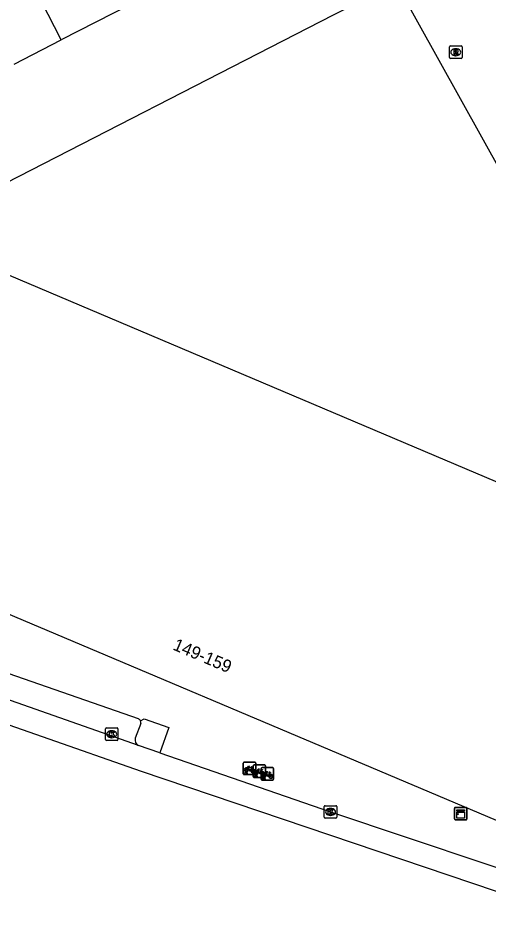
# Model space of a CAD drawing. Extents: x 161771 to 163125, y 382479 to 383177.
# Drawn here: x 162326.1 to 162363.8, y 382570.3 to 382642.4 of the extents above; entities that cross this region are included whole.
import ezdxf

# ---------------------------------------------------------------- set-up
doc = ezdxf.new("R2010")
doc.units = 0
for name, color, linetype in [('IMGEO_Fietsenrek', 7, 'Continuous'), ('IMGEO_Kast', 7, 'Continuous'), ('IMGEO_Kolk', 7, 'Continuous'), ('IMGEO_Pand', 7, 'Continuous'), ('IMGEO_Pand_nummerreeks', 7, 'Continuous'), ('IMGEO_Parkeervlak_open', 7, 'Continuous'), ('IMGEO_Rijbaan_lokaal_gesloten', 7, 'Continuous'), ('IMGEO_Rijbaan_lokaal_open', 7, 'Continuous'), ('IMGEO_Rioolput', 7, 'Continuous'), ('IMGEO_Voetpad_open', 7, 'Continuous')]:
    doc.layers.add(name, color=color, linetype=linetype)

msp = doc.modelspace()

# ---------------------------------------------------------------- linework, layer by layer
at = {"layer": 'IMGEO_Fietsenrek'}
for p, q in [((162344.179, 382581.681), (162344.179, 382582.522)), ((162344.179, 382582.522), (162344.179, 382581.681)), ((162344.254, 382582.606), (162345.095, 382582.606)), ((162345.095, 382582.606), (162344.254, 382582.606)), ((162345.042, 382582.385), (162345.883, 382582.385)), ((162345.883, 382582.385), (162345.042, 382582.385)), ((162345.179, 382582.531), (162345.179, 382581.69)), ((162345.179, 382581.69), (162345.179, 382582.531)), ((162344.306, 382581.69), (162344.345, 382581.85)), ((162344.34, 382581.69), (162344.306, 382581.69)), ((162344.375, 382581.838), (162344.34, 382581.69)), ((162344.417, 382581.862), (162344.416, 382581.866)), ((162344.458, 382581.69), (162344.424, 382581.832)), ((162344.448, 382581.873), (162344.449, 382581.866)), ((162344.456, 382581.836), (162344.491, 382581.69)), ((162344.491, 382581.69), (162344.458, 382581.69)), ((162344.866, 382582.155), (162344.902, 382582.06)), ((162344.967, 382581.46), (162344.967, 382582.301)), ((162344.967, 382582.301), (162344.967, 382581.46)), ((162345.094, 382581.469), (162345.133, 382581.629)), ((162345.163, 382581.617), (162345.128, 382581.469)), ((162345.205, 382581.641), (162345.204, 382581.645)), ((162345.236, 382581.652), (162345.237, 382581.645)), ((162345.244, 382581.615), (162345.279, 382581.469)), ((162345.613, 382581.246), (162345.613, 382582.087)), ((162345.613, 382582.087), (162345.613, 382581.246)), ((162345.654, 382581.934), (162345.69, 382581.839)), ((162345.688, 382582.171), (162346.529, 382582.171)), ((162346.529, 382582.171), (162345.688, 382582.171)), ((162345.967, 382582.31), (162345.967, 382581.469)), ((162345.967, 382581.469), (162345.967, 382582.31)), ((162346.3, 382581.72), (162346.336, 382581.625)), ((162346.613, 382582.096), (162346.613, 382581.255)), ((162346.613, 382581.255), (162346.613, 382582.096)), ((162345.104, 382581.606), (162344.263, 382581.606)), ((162344.263, 382581.606), (162345.104, 382581.606)), ((162345.892, 382581.385), (162345.051, 382581.385)), ((162345.051, 382581.385), (162345.892, 382581.385)), ((162345.128, 382581.469), (162345.094, 382581.469)), ((162345.246, 382581.469), (162345.212, 382581.611)), ((162345.279, 382581.469), (162345.246, 382581.469)), ((162346.538, 382581.171), (162345.697, 382581.171)), ((162345.697, 382581.171), (162346.538, 382581.171)), ((162345.74, 382581.255), (162345.779, 382581.415)), ((162345.774, 382581.255), (162345.74, 382581.255)), ((162345.809, 382581.403), (162345.774, 382581.255)), ((162345.851, 382581.427), (162345.85, 382581.431)), ((162345.892, 382581.255), (162345.858, 382581.397)), ((162345.882, 382581.438), (162345.883, 382581.431)), ((162345.89, 382581.401), (162345.925, 382581.255)), ((162345.925, 382581.255), (162345.892, 382581.255))]:
    msp.add_line(p, q, dxfattribs=at)
for points in [[(162344.513, 382582.08), (162344.461, 382581.99), (162344.421, 382581.965), (162344.422, 382582.012), (162344.477, 382582.106)], [(162344.492, 382582.132), (162344.587, 382582.296), (162344.673, 382582.282), (162344.675, 382582.273), (162344.619, 382582.262), (162344.592, 382582.217), (162344.848, 382582.176)], [(162344.788, 382581.888), (162344.738, 382581.888), (162344.547, 382582.139), (162344.528, 382582.107)], [(162344.835, 382582.151), (162344.578, 382582.192), (162344.561, 382582.163), (162344.728, 382581.943), (162344.835, 382582.151)], [(162344.883, 382582.053), (162344.853, 382582.13), (162344.744, 382581.912), (162344.787, 382581.912)], [(162344.817, 382581.912), (162344.937, 382581.911), (162344.893, 382582.025)], [(162344.913, 382582.032), (162344.968, 382581.887), (162344.818, 382581.887)], [(162344.848, 382582.176), (162344.873, 382582.225), (162344.867, 382582.229), (162344.844, 382582.233), (162344.832, 382582.24), (162344.831, 382582.243), (162344.833, 382582.248), (162344.928, 382582.233), (162344.93, 382582.223), (162344.92, 382582.21), (162344.908, 382582.204), (162344.894, 382582.21), (162344.866, 382582.155)], [(162345.301, 382581.859), (162345.249, 382581.769), (162345.209, 382581.744), (162345.21, 382581.791), (162345.265, 382581.885)], [(162345.28, 382581.911), (162345.375, 382582.075), (162345.461, 382582.061), (162345.463, 382582.052), (162345.407, 382582.041), (162345.38, 382581.996), (162345.636, 382581.955)], [(162345.576, 382581.667), (162345.526, 382581.667), (162345.335, 382581.918), (162345.316, 382581.886)], [(162345.623, 382581.93), (162345.366, 382581.971), (162345.349, 382581.942), (162345.516, 382581.722), (162345.623, 382581.93)], [(162345.671, 382581.832), (162345.641, 382581.909), (162345.532, 382581.691), (162345.575, 382581.691)], [(162345.605, 382581.691), (162345.725, 382581.69), (162345.681, 382581.804)], [(162345.701, 382581.811), (162345.756, 382581.666), (162345.606, 382581.666)], [(162345.636, 382581.955), (162345.661, 382582.004), (162345.655, 382582.008), (162345.632, 382582.012), (162345.62, 382582.019), (162345.619, 382582.022), (162345.621, 382582.027), (162345.716, 382582.012), (162345.718, 382582.002), (162345.708, 382581.989), (162345.696, 382581.983), (162345.682, 382581.989), (162345.654, 382581.934)], [(162345.947, 382581.645), (162345.895, 382581.555), (162345.855, 382581.53), (162345.856, 382581.577), (162345.911, 382581.671)], [(162345.926, 382581.697), (162346.021, 382581.861), (162346.107, 382581.847), (162346.109, 382581.838), (162346.053, 382581.827), (162346.026, 382581.782), (162346.282, 382581.741)], [(162346.222, 382581.453), (162346.172, 382581.453), (162345.981, 382581.704), (162345.962, 382581.672)], [(162346.269, 382581.716), (162346.012, 382581.757), (162345.995, 382581.728), (162346.162, 382581.508), (162346.269, 382581.716)], [(162346.317, 382581.618), (162346.287, 382581.695), (162346.178, 382581.477), (162346.221, 382581.477)], [(162346.282, 382581.741), (162346.307, 382581.79), (162346.301, 382581.794), (162346.278, 382581.798), (162346.266, 382581.805), (162346.265, 382581.808), (162346.267, 382581.813), (162346.362, 382581.798), (162346.364, 382581.788), (162346.354, 382581.775), (162346.342, 382581.769), (162346.328, 382581.775), (162346.3, 382581.72)], [(162346.251, 382581.477), (162346.371, 382581.476), (162346.327, 382581.59)], [(162346.347, 382581.597), (162346.402, 382581.452), (162346.252, 382581.452)]]:
    msp.add_lwpolyline(points, dxfattribs=at)
for centre, radius, start, end in [((162344.257, 382582.528), 0.0779, 92.4484, 184.28452), ((162344.257, 382582.528), 0.0779, 92.4484, 184.28452), ((162345.045, 382582.307), 0.0779, 92.4484, 184.28452), ((162345.045, 382582.307), 0.0779, 92.4484, 184.28452), ((162345.101, 382582.528), 0.0779, 2.4484, 94.28452), ((162345.101, 382582.528), 0.0779, 2.4484, 94.28452), ((162345.889, 382582.307), 0.0779, 2.4484, 94.28452), ((162345.889, 382582.307), 0.0779, 2.4484, 94.28452), ((162344.257, 382581.684), 0.0779, 182.4484, 274.28452), ((162344.257, 382581.684), 0.0779, 182.4484, 274.28452), ((162344.419, 382581.991), 0.159, 62.67661, 242.13685), ((162344.419, 382581.991), 0.129, 63.31916, 238.90302), ((162344.399, 382581.862), 0.0499, 12.8025, 158.69338), ((162344.419, 382581.991), 0.159, 253.99666, 271.78671), ((162344.399, 382581.862), 0.0174, 12.8025, 163.45023), ((162344.419, 382581.991), 0.129, 253.41502, 269.02044), ((162344.419, 382581.991), 0.129, 283.60429, 43.43025), ((162344.419, 382581.991), 0.159, 283.5766, 46.60424), ((162344.946, 382581.907), 0.159, 113.3408, 178.32165), ((162344.946, 382581.907), 0.159, 187.0065, 105.77075), ((162344.946, 382581.907), 0.129, 113.92302, 177.95563), ((162344.946, 382581.907), 0.129, 188.67146, 104.58832), ((162345.207, 382581.77), 0.159, 62.67661, 242.13685), ((162345.207, 382581.77), 0.129, 63.31916, 238.90302), ((162345.101, 382581.684), 0.0779, 272.4484, 4.28452), ((162345.101, 382581.684), 0.0779, 272.4484, 4.28452), ((162345.187, 382581.641), 0.0499, 12.8025, 158.69338), ((162345.207, 382581.77), 0.159, 253.99666, 271.78671), ((162345.187, 382581.641), 0.0174, 12.8025, 163.45023), ((162345.207, 382581.77), 0.129, 253.41502, 269.02044), ((162345.207, 382581.77), 0.129, 283.60429, 43.43025), ((162345.207, 382581.77), 0.159, 283.5766, 46.60424), ((162345.734, 382581.686), 0.159, 113.3408, 178.32165), ((162345.734, 382581.686), 0.159, 187.0065, 105.77075), ((162345.734, 382581.686), 0.129, 113.92302, 177.95563), ((162345.734, 382581.686), 0.129, 188.67146, 104.58832), ((162345.691, 382582.093), 0.0779, 92.4484, 184.28452), ((162345.691, 382582.093), 0.0779, 92.4484, 184.28452), ((162345.853, 382581.556), 0.159, 62.67661, 242.13685), ((162345.853, 382581.556), 0.129, 63.31916, 238.90302), ((162345.853, 382581.556), 0.129, 283.60429, 43.43025), ((162345.853, 382581.556), 0.159, 283.5766, 46.60424), ((162346.38, 382581.472), 0.159, 113.3408, 178.32165), ((162346.38, 382581.472), 0.159, 187.0065, 105.77075), ((162346.535, 382582.093), 0.0779, 2.4484, 94.28452), ((162346.535, 382582.093), 0.0779, 2.4484, 94.28452), ((162345.045, 382581.463), 0.0779, 182.4484, 274.28452), ((162345.045, 382581.463), 0.0779, 182.4484, 274.28452), ((162345.691, 382581.249), 0.0779, 182.4484, 274.28452), ((162345.691, 382581.249), 0.0779, 182.4484, 274.28452), ((162345.833, 382581.427), 0.0499, 12.8025, 158.69338), ((162345.853, 382581.556), 0.159, 253.99666, 271.78671), ((162345.833, 382581.427), 0.0174, 12.8025, 163.45023), ((162345.853, 382581.556), 0.129, 253.41502, 269.02044), ((162345.889, 382581.463), 0.0779, 272.4484, 4.28452), ((162345.889, 382581.463), 0.0779, 272.4484, 4.28452), ((162346.38, 382581.472), 0.129, 113.92302, 177.95563), ((162346.38, 382581.472), 0.129, 188.67146, 104.58832), ((162346.535, 382581.249), 0.0779, 272.4484, 4.28452), ((162346.535, 382581.249), 0.0779, 272.4484, 4.28452)]:
    msp.add_arc(centre, radius, start, end, dxfattribs=at)
at = {"layer": 'IMGEO_Kast'}
for p, q in [((162361.122, 382578.055), (162361.122, 382578.896)), ((162361.122, 382578.896), (162361.122, 382578.055)), ((162361.197, 382578.98), (162362.038, 382578.98)), ((162362.038, 382578.98), (162361.197, 382578.98)), ((162362.122, 382578.905), (162362.122, 382578.064)), ((162362.122, 382578.064), (162362.122, 382578.905)), ((162362.047, 382577.98), (162361.206, 382577.98)), ((162361.206, 382577.98), (162362.047, 382577.98))]:
    msp.add_line(p, q, dxfattribs=at)
for points in [[(162361.317, 382578.77), (162361.917, 382578.77), (162361.917, 382578.685), (162361.317, 382578.685), (162361.317, 382578.77)], [(162361.317, 382578.595), (162361.917, 382578.595), (162361.917, 382578.106), (162361.317, 382578.106), (162361.317, 382578.595)]]:
    msp.add_lwpolyline(points, dxfattribs=at)
msp.add_circle((162361.401, 382578.444), 0.0377, dxfattribs=at)
for centre, start, end in [((162361.2, 382578.902), 92.4484, 184.28452), ((162361.2, 382578.902), 92.4484, 184.28452), ((162362.044, 382578.902), 2.4484, 94.28452), ((162362.044, 382578.902), 2.4484, 94.28452), ((162361.2, 382578.058), 182.4484, 274.28452), ((162361.2, 382578.058), 182.4484, 274.28452), ((162362.044, 382578.058), 272.4484, 4.28452), ((162362.044, 382578.058), 272.4484, 4.28452)]:
    msp.add_arc(centre, 0.0779, start, end, dxfattribs=at)
at = {"layer": 'IMGEO_Kolk'}
for p, q in [((162333.123, 382584.425), (162333.123, 382585.277)), ((162333.198, 382585.351), (162334.05, 382585.351)), ((162334.124, 382585.277), (162334.124, 382584.425)), ((162333.634, 382584.571), (162333.609, 382584.571)), ((162333.611, 382585.131), (162333.636, 382585.131)), ((162334.05, 382584.351), (162333.198, 382584.351)), ((162350.678, 382578.187), (162350.678, 382579.039)), ((162350.753, 382579.113), (162351.605, 382579.113)), ((162351.166, 382578.893), (162351.191, 382578.893)), ((162351.679, 382579.039), (162351.679, 382578.187)), ((162351.605, 382578.113), (162350.753, 382578.113)), ((162351.189, 382578.333), (162351.164, 382578.333))]:
    msp.add_line(p, q, dxfattribs=at)
for points in [[(162333.123, 382584.425), (162333.123, 382585.277)], [(162333.198, 382585.351), (162334.05, 382585.351)], [(162334.124, 382585.277), (162334.124, 382584.425)], [(162333.444, 382585.051), (162333.567, 382585.051), (162333.567, 382584.9), (162333.697, 382585.051), (162333.861, 382585.051), (162333.715, 382584.9), (162333.868, 382584.651), (162333.716, 382584.651), (162333.631, 382584.815), (162333.567, 382584.748), (162333.567, 382584.651), (162333.444, 382584.651), (162333.444, 382585.051)], [(162334.05, 382584.351), (162333.198, 382584.351)], [(162350.678, 382578.187), (162350.678, 382579.039)], [(162350.753, 382579.113), (162351.605, 382579.113)], [(162350.999, 382578.813), (162351.122, 382578.813), (162351.122, 382578.662), (162351.252, 382578.813), (162351.416, 382578.813), (162351.27, 382578.662), (162351.423, 382578.413), (162351.271, 382578.413), (162351.186, 382578.577), (162351.122, 382578.51), (162351.122, 382578.413), (162350.999, 382578.413), (162350.999, 382578.813)], [(162351.679, 382579.039), (162351.679, 382578.187)], [(162351.605, 382578.113), (162350.753, 382578.113)]]:
    msp.add_lwpolyline(points, dxfattribs=at)
for centre, start, end in [((162333.2, 382585.275), 91.55205, 178.44795), ((162333.2, 382585.275), 91.55205, 178.44795), ((162334.048, 382585.275), 1.55205, 88.44795), ((162334.048, 382585.275), 1.55205, 88.44795), ((162333.2, 382584.427), 181.55205, 268.44795), ((162333.2, 382584.427), 181.55205, 268.44795), ((162334.048, 382584.427), 271.55205, 358.44795), ((162334.048, 382584.427), 271.55205, 358.44795), ((162350.755, 382579.037), 91.55205, 178.44795), ((162350.755, 382579.037), 91.55205, 178.44795), ((162351.603, 382579.037), 1.55205, 88.44795), ((162351.603, 382579.037), 1.55205, 88.44795), ((162350.755, 382578.189), 181.55205, 268.44795), ((162350.755, 382578.189), 181.55205, 268.44795), ((162351.603, 382578.189), 271.55205, 358.44795), ((162351.603, 382578.189), 271.55205, 358.44795)]:
    msp.add_arc(centre, 0.0765, start, end, dxfattribs=at)
for centre, major_axis, ratio, start_param, end_param in [((162333.61, 382584.851), (-0.387, 0.002), 0.722429, 4.712389, 7.853982), ((162333.635, 382584.851), (-0.39, 0.002), 0.717154, 1.570796, 4.712389), ((162351.165, 382578.613), (-0.387, 0.002), 0.722429, 4.712389, 7.853982), ((162351.19, 382578.613), (-0.39, 0.002), 0.717154, 1.570796, 4.712389)]:
    msp.add_ellipse(centre, major_axis=major_axis, ratio=ratio, start_param=start_param, end_param=end_param, dxfattribs=at)
at = {"layer": 'IMGEO_Pand'}
for points in [[(162329.566, 382640.609), (162326.409, 382646.789), (162344.176, 382655.844), (162344.436, 382655.843), (162345.668, 382653.406), (162348.747, 382654.979)], [(162350.456, 382651.281), (162329.566, 382640.609)], [(162355.836, 382644.864), (162351.387, 382642.583), (162322.08, 382627.559), (162320.518, 382630.266), (162318.547, 382629.128), (162316.196, 382633.711)], [(162325.796, 382638.664), (162329.566, 382640.609)], [(162379.028, 382608.247), (162375.863, 382604.377), (162373.376, 382601.335), (162322.929, 382622.738)], [(162368.518, 382576.348), (162368.466, 382576.233), (162313.172, 382599.641)]]:
    msp.add_lwpolyline(points, dxfattribs=at)
at = {"layer": 'IMGEO_Parkeervlak_open'}
msp.add_lwpolyline([(162335.962, 382585.724), (162335.516, 382584.532)], dxfattribs=at)
for centre, radius, start, end in [((162335.594, 382585.759), 0.369, 354.60434, 25.37775), ((162335.988, 382584.385), 0.494, 162.70994, 245.64176)]:
    msp.add_arc(centre, radius, start, end, dxfattribs=at)
at = {"layer": 'IMGEO_Rijbaan_lokaal_gesloten'}
for points in [[(162370.099, 382570.33), (162336, 382581.86), (162312.157, 382590.208), (162289.771, 382599.475), (162259.358, 382612.5), (162215.386, 382631.365)], [(162335.784, 382583.935), (162312.409, 382592.158)], [(162337.494, 382583.35), (162335.784, 382583.935)], [(162337.494, 382583.35), (162351.179, 382578.613), (162369.708, 382572.396), (162369.783, 382572.369)]]:
    msp.add_lwpolyline(points, dxfattribs=at)
at = {"layer": 'IMGEO_Rijbaan_lokaal_open'}
msp.add_lwpolyline([(162379.028, 382608.247), (162375.169, 382611.496), (162356.474, 382645.131), (162355.836, 382644.864)], dxfattribs=at)
at = {"layer": 'IMGEO_Rioolput'}
for p, q in [((162360.722, 382639.193), (162360.722, 382640.045)), ((162360.797, 382640.119), (162361.649, 382640.119)), ((162361.723, 382640.045), (162361.723, 382639.193)), ((162361.233, 382639.339), (162361.208, 382639.339)), ((162361.21, 382639.899), (162361.235, 382639.899)), ((162361.649, 382639.119), (162360.797, 382639.119))]:
    msp.add_line(p, q, dxfattribs=at)
for points in [[(162360.722, 382639.193), (162360.722, 382640.045)], [(162360.797, 382640.119), (162361.649, 382640.119)], [(162361.723, 382640.045), (162361.723, 382639.193)], [(162361.311, 382639.817), (162361.059, 382639.819), (162361.059, 382639.419)], [(162361.059, 382639.419), (162361.183, 382639.419), (162361.183, 382639.581), (162361.194, 382639.581)], [(162361.237, 382639.738), (162361.183, 382639.738), (162361.183, 382639.657)], [(162361.183, 382639.657), (162361.235, 382639.657)], [(162361.241, 382639.552), (162361.312, 382639.419), (162361.452, 382639.419), (162361.387, 382639.545)], [(162361.649, 382639.119), (162360.797, 382639.119)]]:
    msp.add_lwpolyline(points, dxfattribs=at)
for centre, radius, start, end in [((162360.799, 382640.043), 0.0765, 91.55205, 178.44795), ((162360.799, 382640.043), 0.0765, 91.55205, 178.44795), ((162361.647, 382640.043), 0.0765, 1.55205, 88.44795), ((162361.647, 382640.043), 0.0765, 1.55205, 88.44795), ((162361.193, 382639.528), 0.0533, 26.02933, 88.69889), ((162361.219, 382639.846), 0.19, 274.7715, 282.96867), ((162361.243, 382639.642), 0.0964, 77.00612, 93.18647), ((162361.257, 382639.699), 0.0378, 276.66336, 79.67722), ((162361.31, 382639.707), 0.109, 350.36119, 89.41601), ((162361.308, 382639.707), 0.112, 277.58423, 350.98172), ((162361.292, 382639.492), 0.108, 29.51342, 73.79051), ((162360.799, 382639.195), 0.0765, 181.55205, 268.44795), ((162360.799, 382639.195), 0.0765, 181.55205, 268.44795), ((162361.647, 382639.195), 0.0765, 271.55205, 358.44795), ((162361.647, 382639.195), 0.0765, 271.55205, 358.44795)]:
    msp.add_arc(centre, radius, start, end, dxfattribs=at)
for centre, major_axis, ratio, start_param, end_param in [((162361.209, 382639.619), (-0.387, 0.002), 0.722429, 4.712389, 7.853982), ((162361.234, 382639.619), (-0.39, 0.002), 0.717154, 1.570796, 4.712389)]:
    msp.add_ellipse(centre, major_axis=major_axis, ratio=ratio, start_param=start_param, end_param=end_param, dxfattribs=at)
at = {"layer": 'IMGEO_Voetpad_open'}
for points in [[(162313.828, 382593.798), (162323.501, 382590.382), (162335.732, 382586.104)], [(162335.928, 382585.917), (162336.224, 382586.083), (162338.213, 382585.379), (162337.494, 382583.35)]]:
    msp.add_lwpolyline(points, dxfattribs=at)
msp.add_arc((162335.587, 382585.755), 0.378, 25.33246, 67.35979, dxfattribs=at)

# ---------------------------------------------------------------- texts
at = {"layer": 'IMGEO_Pand_nummerreeks'}
msp.add_text('149-159', height=1, rotation=336.94991, dxfattribs=at).set_placement((162338.459, 382591.668))

doc.saveas('drawing.dxf')
